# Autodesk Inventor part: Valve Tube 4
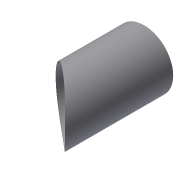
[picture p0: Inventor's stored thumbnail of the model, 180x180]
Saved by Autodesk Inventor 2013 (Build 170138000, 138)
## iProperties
Created: 2012-08
Part Number: Valve Tube 4
Document SubType Name: Modeling
Designer: dms52
Density: 1 g/cm^3
Material: Generic
Author: dms52
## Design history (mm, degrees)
sketch "Sketch1"
  geometry: C1 r 38.1 at (0, 0); C2 r 36.449 at (0, 0); 1 further point
  constraints: 2 centre point, 2 coincident
  dimensions: "d0" = 1.651 radial gap between concentric circles of C1 C2; "d1" = 76.2 diameter of C1
extrude "Extrusion1" new body sketch "Sketch1" distance "d2" = 177.8; taper "d3" = 0 deg
sketch "Sketch3"
  geometry: L1 (0, -279.964)-(0, 1434.232) reference; L2 (-38.1, 0)-(38.1, 0) reference; C1 r 476.25 at (304.8, 472.44); 1 further point
  constraints: 1 centre point
  dimensions: "d6" = 952.5 diameter of C1; "d7" = 304.8 distance from line of L1 C1.centre; "d8" = 472.44 distance from line of L2 C1.centre
extrude "Extrusion3" cut sketch "Sketch3" stored distance "d9" = 0; taper "d10" = 0 deg
body "Solid1"
